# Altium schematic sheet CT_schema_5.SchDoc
size 165 x 142 mm
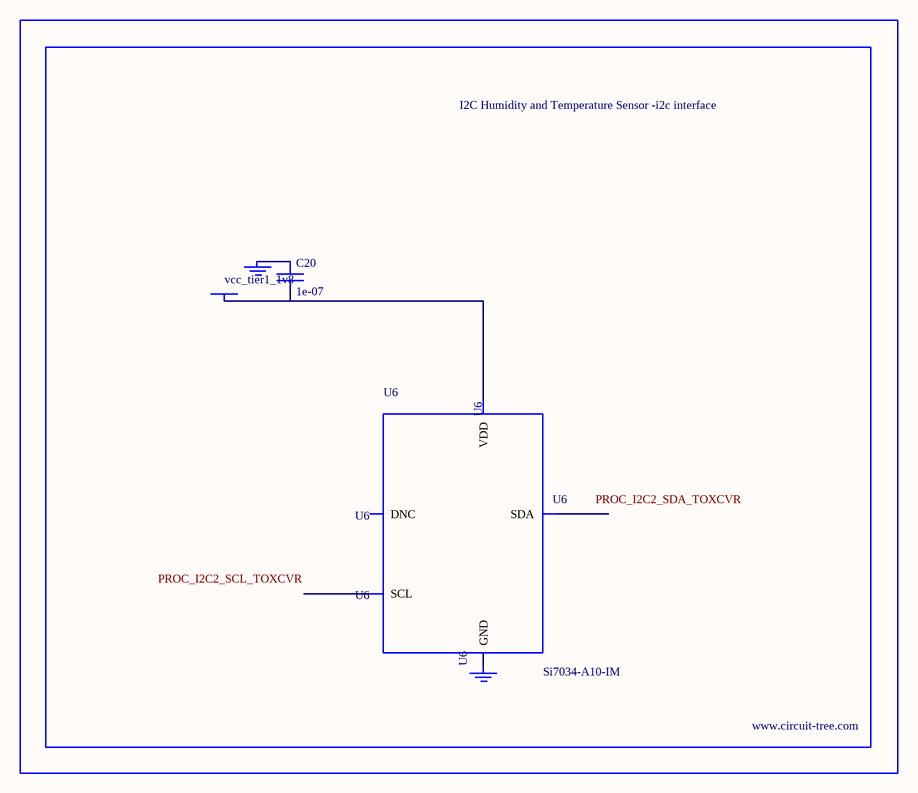
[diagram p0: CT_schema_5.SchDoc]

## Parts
BORDER4  (no value)
C20  1e-07  [C0402]
GND_INSTANCE_4_0  (no value)
GND_INSTANCE_4_1  (no value)
POWER_INSTANCE_4_0  vcc_tier1_1v8
U6  Si7034-A10-IM  [SI7034-A10-IM]

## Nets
NetC20_1: C20.1 GND_INSTANCE_4_0.0(GND)
NetC20_2: C20.2 POWER_INSTANCE_4_0.0(PWR) U6.1(VDD)
NetGND_INSTANCE_4_1_0: GND_INSTANCE_4_1.0(GND) U6.5(GND)

Not connected (* = marked no-connect by the designer): U6 2(SCL) 3(DNC) 4(SDA)

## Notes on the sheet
- Labels drawn without touching a wire or pin: PROC_I2C2_SCL_TOXCVR, PROC_I2C2_SDA_TOXCVR

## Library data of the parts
BORDER4 = BORDER_PAGE4
C20 = C0402C104K3RACTU
GND_INSTANCE_4_0 GND_INSTANCE_4_1 = GND
POWER_INSTANCE_4_0 = PWR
